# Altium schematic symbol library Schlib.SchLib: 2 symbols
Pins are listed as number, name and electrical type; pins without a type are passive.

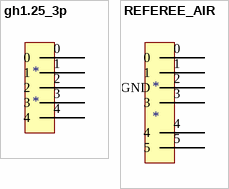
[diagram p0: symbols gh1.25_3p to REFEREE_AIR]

## gh1.25_3p
designator *
footprint GH1.25-LS-3P (A1257WR-S-3P)
pins: 0, 1, 2, 3, 4

## REFEREE_AIR
designator *
pins: 0, 1, 2 GND, 3, 4, 5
